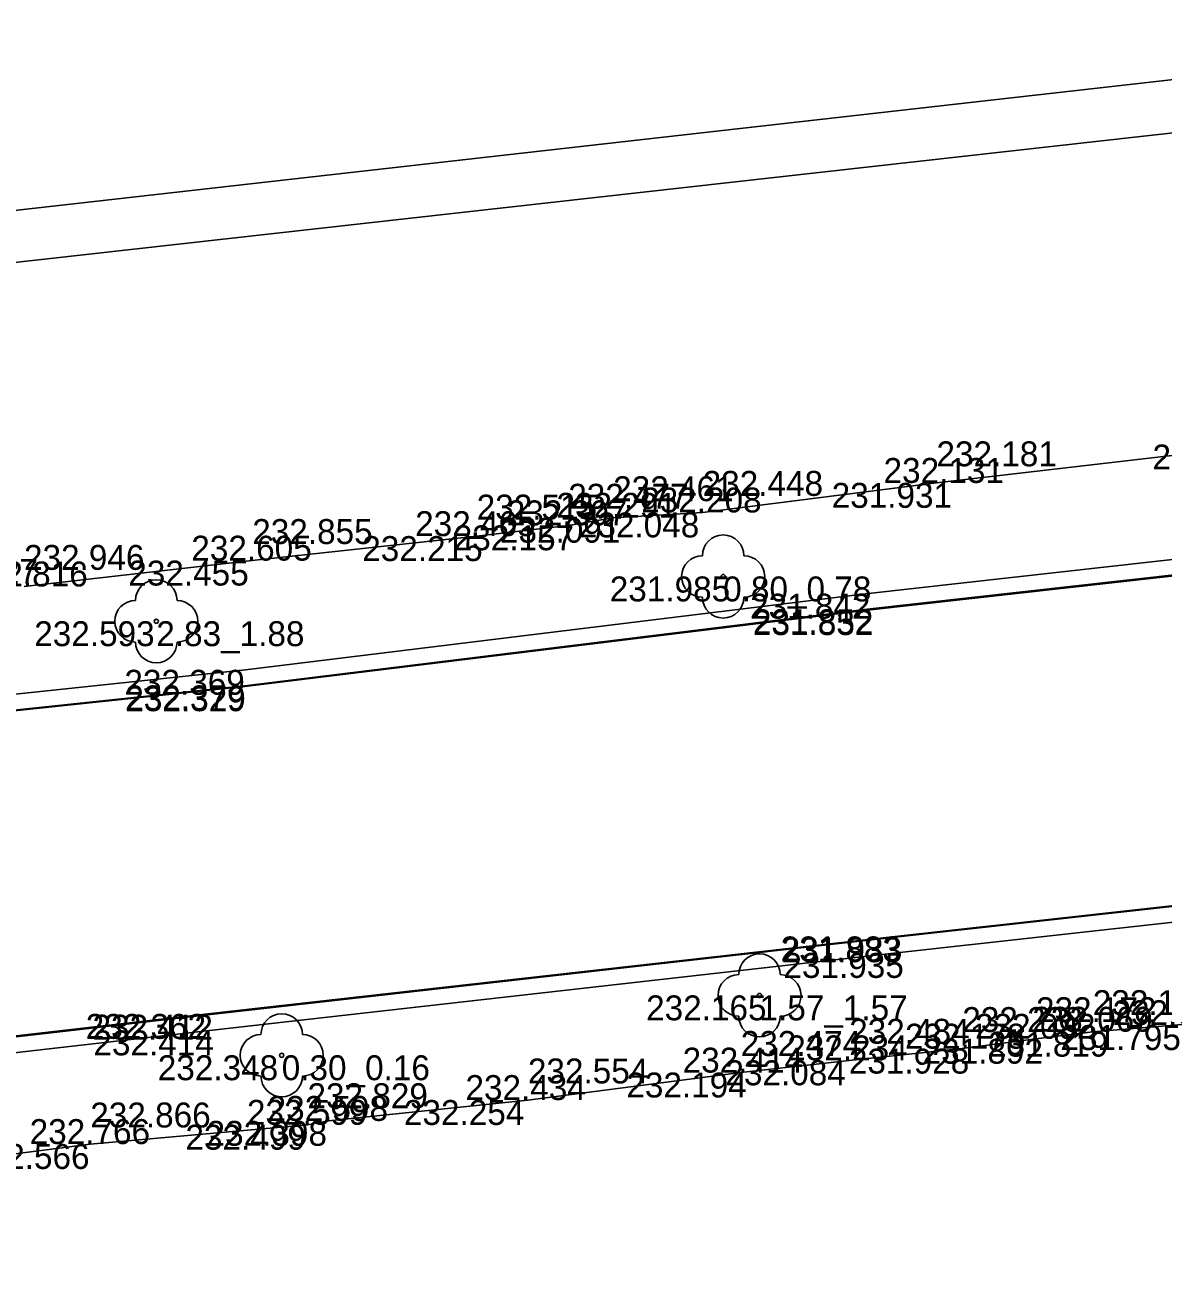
# Model space of a CAD drawing. Extents: x -599516 to -599132, y -1163668 to -1163119.
# Drawn here: x -599469.23 to -599455.52, y -1163522.85 to -1163507.88 of the extents above; entities that cross this region are included whole.
import ezdxf

# ---------------------------------------------------------------- set-up
doc = ezdxf.new("R2010")
doc.units = 0
for name, color, linetype in [('Bod-oznac1', 7, 'Continuous'), ('Bod-oznac2', 7, 'Continuous'), ('Bod-oznac3', 7, 'Continuous'), ('Bod-vyska1', 7, 'Continuous'), ('Bod-vyska2', 7, 'Continuous'), ('Bod-vyska3', 7, 'Continuous'), ('Z_cela-hrobu-dolni-linie', 7, 'Continuous'), ('Z_cela-hrobu-horni-linie', 7, 'Continuous'), ('Z_komunikace', 7, 'Continuous'), ('Z_obvod-kmene-spodek-ve-vysce1_2m', 7, 'Continuous'), ('Z_stromy-kere', 7, 'Continuous'), ('Z_zdi-ohradni', 7, 'Continuous'), ('Z_zpevnene-plochy', 7, 'Continuous')]:
    doc.layers.add(name, color=color, linetype=linetype)

msp = doc.modelspace()

# ---------------------------------------------------------------- linework, layer by layer
at = {"layer": 'Bod-oznac1'}
for p, q in [((-599458.25, -1163513.395), (-599458.25, -1163513.395)), ((-599461.066, -1163513.751), (-599461.066, -1163513.751)), ((-599462.685, -1163513.906), (-599462.685, -1163513.906)), ((-599462.144, -1163513.815), (-599462.144, -1163513.815)), ((-599463.788, -1163514.036), (-599463.788, -1163514.036)), ((-599466.491, -1163514.331), (-599466.491, -1163514.331)), ((-599460.819, -1163514.522), (-599460.819, -1163514.522)), ((-599459.106, -1163514.729), (-599459.106, -1163514.729)), ((-599459.083, -1163514.917), (-599459.083, -1163514.917)), ((-599459.082, -1163514.927), (-599459.082, -1163514.927)), ((-599467.647, -1163515.061), (-599467.647, -1163515.061)), ((-599466.572, -1163515.646), (-599466.572, -1163515.646)), ((-599466.55, -1163515.834), (-599466.55, -1163515.834)), ((-599466.549, -1163515.844), (-599466.549, -1163515.844)), ((-599458.749, -1163518.857), (-599458.749, -1163518.857)), ((-599458.748, -1163518.867), (-599458.748, -1163518.867)), ((-599458.727, -1163519.056), (-599458.727, -1163519.056)), ((-599460.381, -1163519.567), (-599460.381, -1163519.567)), ((-599467.027, -1163519.79), (-599467.027, -1163519.79)), ((-599467.026, -1163519.8), (-599467.026, -1163519.8)), ((-599467.004, -1163519.989), (-599467.004, -1163519.989)), ((-599456.367, -1163520.004), (-599456.367, -1163520.004)), ((-599457.939, -1163520.208), (-599457.939, -1163520.208)), ((-599457.051, -1163520.089), (-599457.051, -1163520.089)), ((-599466.136, -1163520.288), (-599466.136, -1163520.288)), ((-599459.301, -1163520.349), (-599459.301, -1163520.349)), ((-599460.607, -1163520.496), (-599460.607, -1163520.496)), ((-599463.171, -1163520.827), (-599463.171, -1163520.827)), ((-599465.571, -1163521.078), (-599465.571, -1163521.078)), ((-599465.826, -1163521.125), (-599465.826, -1163521.125)), ((-599468.442, -1163521.357), (-599468.442, -1163521.357))]:
    msp.add_line(p, q, dxfattribs=at)
at = {"layer": 'Bod-oznac2'}
for p, q in [((-599458.25, -1163513.395), (-599458.25, -1163513.395)), ((-599461.066, -1163513.751), (-599461.066, -1163513.751)), ((-599462.685, -1163513.906), (-599462.685, -1163513.906)), ((-599462.144, -1163513.815), (-599462.144, -1163513.815)), ((-599463.788, -1163514.036), (-599463.788, -1163514.036)), ((-599466.491, -1163514.331), (-599466.491, -1163514.331)), ((-599456.367, -1163520.004), (-599456.367, -1163520.004)), ((-599457.939, -1163520.208), (-599457.939, -1163520.208)), ((-599457.051, -1163520.089), (-599457.051, -1163520.089)), ((-599459.301, -1163520.349), (-599459.301, -1163520.349)), ((-599460.607, -1163520.496), (-599460.607, -1163520.496)), ((-599463.171, -1163520.827), (-599463.171, -1163520.827)), ((-599465.571, -1163521.078), (-599465.571, -1163521.078)), ((-599465.826, -1163521.125), (-599465.826, -1163521.125)), ((-599468.442, -1163521.357), (-599468.442, -1163521.357))]:
    msp.add_line(p, q, dxfattribs=at)
at = {"layer": 'Bod-oznac3'}
for p, q in [((-599458.25, -1163513.395), (-599458.25, -1163513.395)), ((-599461.066, -1163513.751), (-599461.066, -1163513.751)), ((-599462.685, -1163513.906), (-599462.685, -1163513.906)), ((-599462.144, -1163513.815), (-599462.144, -1163513.815)), ((-599463.788, -1163514.036), (-599463.788, -1163514.036)), ((-599466.491, -1163514.331), (-599466.491, -1163514.331)), ((-599456.367, -1163520.004), (-599456.367, -1163520.004)), ((-599457.939, -1163520.208), (-599457.939, -1163520.208)), ((-599457.051, -1163520.089), (-599457.051, -1163520.089)), ((-599459.301, -1163520.349), (-599459.301, -1163520.349)), ((-599460.607, -1163520.496), (-599460.607, -1163520.496)), ((-599463.171, -1163520.827), (-599463.171, -1163520.827)), ((-599465.826, -1163521.125), (-599465.826, -1163521.125)), ((-599468.442, -1163521.357), (-599468.442, -1163521.357))]:
    msp.add_line(p, q, dxfattribs=at)
at = {"layer": 'Z_cela-hrobu-dolni-linie'}
for points in [[(-599435.23, -1163510.833), (-599438.008, -1163511.099), (-599439.418, -1163511.294), (-599442.084, -1163511.555), (-599442.667, -1163511.633), (-599443.058, -1163511.684), (-599443.507, -1163511.738), (-599444.573, -1163511.832), (-599445.156, -1163511.901), (-599446.188, -1163512.018), (-599447.56, -1163512.189), (-599449.119, -1163512.348), (-599449.987, -1163512.469), (-599451.605, -1163512.656), (-599454.27, -1163512.933), (-599458.25, -1163513.395), (-599461.066, -1163513.751), (-599462.144, -1163513.815), (-599462.685, -1163513.906), (-599463.788, -1163514.036), (-599466.491, -1163514.331), (-599469.24, -1163514.642)], [(-599470.95, -1163521.715), (-599470.845, -1163521.668), (-599468.442, -1163521.357), (-599465.826, -1163521.125), (-599465.571, -1163521.078), (-599463.171, -1163520.827), (-599460.607, -1163520.496), (-599459.301, -1163520.349), (-599457.939, -1163520.208), (-599457.051, -1163520.089), (-599456.367, -1163520.004), (-599455.388, -1163519.925), (-599454.061, -1163519.809), (-599451.356, -1163519.55)]]:
    msp.add_lwpolyline(points, dxfattribs=at)
at = {"layer": 'Z_cela-hrobu-horni-linie'}
for points in [[(-599454.27, -1163512.933), (-599458.25, -1163513.395), (-599458.25, -1163513.395), (-599461.066, -1163513.751), (-599461.066, -1163513.751), (-599462.144, -1163513.815), (-599462.144, -1163513.815), (-599462.685, -1163513.906), (-599462.685, -1163513.906), (-599463.788, -1163514.036), (-599463.788, -1163514.036), (-599466.491, -1163514.331), (-599466.491, -1163514.331), (-599469.24, -1163514.642)], [(-599470.845, -1163521.668), (-599468.442, -1163521.357), (-599468.442, -1163521.357), (-599465.826, -1163521.125), (-599465.826, -1163521.125), (-599465.571, -1163521.078), (-599463.171, -1163520.827), (-599463.171, -1163520.827), (-599460.607, -1163520.496), (-599460.607, -1163520.496), (-599459.301, -1163520.349), (-599459.301, -1163520.349), (-599457.939, -1163520.208), (-599457.939, -1163520.208), (-599457.051, -1163520.089), (-599457.051, -1163520.089), (-599456.367, -1163520.004), (-599456.367, -1163520.004), (-599455.388, -1163519.925), (-599455.388, -1163519.925), (-599454.061, -1163519.809), (-599454.061, -1163519.809), (-599451.356, -1163519.55), (-599451.107, -1163522.776)]]:
    msp.add_lwpolyline(points, dxfattribs=at)
at = {"layer": 'Z_komunikace'}
for points in [[(-599473.086, -1163516.534), (-599466.549, -1163515.844), (-599459.082, -1163514.927), (-599451.472, -1163514.076), (-599444.032, -1163513.231), (-599437.09, -1163512.446), (-599427.751, -1163511.414), (-599421.407, -1163510.664)], [(-599421.581, -1163514.662), (-599428.36, -1163515.423), (-599434.819, -1163516.148), (-599441.683, -1163516.929), (-599449.913, -1163517.876), (-599458.749, -1163518.857), (-599467.027, -1163519.79), (-599473.501, -1163520.532), (-599473.927, -1163520.461), (-599474.378, -1163520.597), (-599474.641, -1163520.812), (-599479.573, -1163521.271)]]:
    msp.add_lwpolyline(points, dxfattribs=at)
at = {"layer": 'Z_stromy-kere'}
for centre in [(-599460.819, -1163514.522), (-599467.647, -1163515.061), (-599460.381, -1163519.567), (-599466.136, -1163520.288)]:
    msp.add_circle(centre, 0.025, dxfattribs=at)
for centre, start, end in [((-599460.819, -1163514.272), 0, 180), ((-599461.069, -1163514.522), 90, 270), ((-599460.569, -1163514.522), 270, 90), ((-599467.647, -1163514.811), 0, 180), ((-599467.897, -1163515.061), 90, 270), ((-599467.397, -1163515.061), 270, 90), ((-599460.819, -1163514.772), 180, 0), ((-599467.647, -1163515.311), 180, 0), ((-599460.381, -1163519.317), 0, 180), ((-599460.631, -1163519.567), 90, 270), ((-599460.131, -1163519.567), 270, 90), ((-599466.136, -1163520.038), 0, 180), ((-599460.381, -1163519.817), 180, 0), ((-599466.386, -1163520.288), 90, 270), ((-599465.886, -1163520.288), 270, 90), ((-599466.136, -1163520.538), 180, 0)]:
    msp.add_arc(centre, 0.25, start, end, dxfattribs=at)
at = {"layer": 'Z_zdi-ohradni'}
for p, q in [((-599421.833, -1163504.754), (-599479.244, -1163511.228)), ((-599479.185, -1163511.843), (-599421.751, -1163505.409))]:
    msp.add_line(p, q, dxfattribs=at)
at = {"layer": 'Z_zpevnene-plochy'}
for points in [[(-599473.087, -1163516.524), (-599473.107, -1163516.335), (-599466.572, -1163515.646), (-599459.106, -1163514.729), (-599451.495, -1163513.878), (-599444.055, -1163513.033), (-599437.113, -1163512.248), (-599427.774, -1163511.216), (-599421.459, -1163510.469), (-599421.021, -1163510.284), (-599420.396, -1163509.389), (-599420.24, -1163509.498)], [(-599473.087, -1163516.524), (-599466.55, -1163515.834), (-599459.083, -1163514.917), (-599451.473, -1163514.066), (-599444.033, -1163513.221), (-599437.091, -1163512.436), (-599427.752, -1163511.404), (-599421.41, -1163510.654), (-599420.897, -1163510.438), (-599420.24, -1163509.498)], [(-599419.671, -1163519.873), (-599419.717, -1163516.476), (-599420.045, -1163515.835), (-599420.256, -1163515.089), (-599420.887, -1163514.692), (-599421.581, -1163514.672), (-599428.359, -1163515.433), (-599434.818, -1163516.158), (-599441.682, -1163516.939), (-599449.912, -1163517.886), (-599458.748, -1163518.867), (-599467.026, -1163519.8), (-599473.501, -1163520.542), (-599473.926, -1163520.471), (-599474.373, -1163520.606), (-599474.637, -1163520.822), (-599479.572, -1163521.281), (-599480.282, -1163521.415), (-599480.802, -1163521.956), (-599481.292, -1163522.751)], [(-599419.671, -1163519.873), (-599419.861, -1163519.876), (-599419.906, -1163516.524), (-599420.223, -1163515.904), (-599420.418, -1163515.211), (-599420.944, -1163514.88), (-599421.573, -1163514.862), (-599428.338, -1163515.622), (-599434.796, -1163516.347), (-599441.66, -1163517.128), (-599449.89, -1163518.075), (-599458.727, -1163519.056), (-599467.004, -1163519.989), (-599473.506, -1163520.734), (-599473.914, -1163520.666), (-599474.282, -1163520.777), (-599474.562, -1163521.005), (-599479.545, -1163521.469), (-599480.187, -1163521.591), (-599480.651, -1163522.073), (-599481.13, -1163522.851), (-599481.292, -1163522.751)]]:
    msp.add_lwpolyline(points, dxfattribs=at)

# ---------------------------------------------------------------- texts
at = {"layer": 'Bod-vyska1'}
for s, p in [('231.684', (-599455.648, -1163513.233)), ('231.931', (-599459.512, -1163513.695)), ('232.048', (-599462.557, -1163514.051)), ('232.157', (-599464.064, -1163514.206)), ('232.091', (-599463.508, -1163514.115)), ('232.215', (-599465.166, -1163514.336)), ('232.455', (-599467.984, -1163514.631)), ('231.985', (-599462.185, -1163514.822)), ('231.842', (-599460.495, -1163515.029)), ('231.852', (-599460.461, -1163515.217)), ('231.832', (-599460.46, -1163515.227)), ('232.593', (-599469.117, -1163515.361)), ('232.369', (-599468.031, -1163515.946)), ('232.379', (-599468.022, -1163516.134)), ('232.329', (-599468.019, -1163516.144)), ('231.883', (-599460.127, -1163519.157)), ('231.933', (-599460.114, -1163519.167)), ('231.935', (-599460.093, -1163519.356)), ('232.165', (-599461.747, -1163519.867)), ('232.362', (-599468.497, -1163520.09)), ('232.412', (-599468.415, -1163520.1)), ('231.795', (-599456.756, -1163520.225)), ('232.414', (-599468.404, -1163520.289)), ('231.819', (-599457.629, -1163520.304)), ('231.928', (-599459.305, -1163520.508)), ('231.892', (-599458.417, -1163520.389)), ('232.348', (-599467.629, -1163520.588)), ('232.084', (-599460.792, -1163520.649)), ('232.194', (-599461.985, -1163520.796)), ('232.254', (-599464.664, -1163521.127)), ('232.499', (-599467.296, -1163521.425)), ('232.398', (-599467.041, -1163521.378)), ('232.566', (-599469.901, -1163521.657))]:
    msp.add_text(s, height=0.3, dxfattribs=at).set_placement(p)
at = {"layer": 'Bod-vyska2'}
for s, p in [('232.131', (-599458.887, -1163513.395)), ('232.208', (-599461.806, -1163513.751)), ('232.307', (-599463.426, -1163513.906)), ('232.291', (-599462.827, -1163513.815)), ('232.465', (-599464.529, -1163514.036)), ('232.605', (-599467.225, -1163514.331)), ('232.816', (-599469.923, -1163514.642)), ('232.075', (-599456.129, -1163519.925)), ('232.069', (-599457.095, -1163520.004)), ('232.178', (-599458.629, -1163520.208)), ('232.092', (-599457.785, -1163520.089)), ('232.234', (-599460.047, -1163520.349)), ('232.414', (-599461.307, -1163520.496)), ('232.434', (-599463.923, -1163520.827)), ('232.599', (-599466.555, -1163521.125)), ('232.598', (-599466.306, -1163521.078)), ('232.766', (-599469.172, -1163521.357))]:
    msp.add_text(s, height=0.3, dxfattribs=at).set_placement(p)
at = {"layer": 'Bod-vyska3'}
for s, p in [('232.181', (-599458.25, -1163513.195)), ('232.461', (-599462.144, -1163513.615)), ('232.448', (-599461.066, -1163513.551)), ('232.477', (-599462.685, -1163513.706)), ('232.515', (-599463.788, -1163513.836)), ('232.855', (-599466.491, -1163514.131)), ('232.946', (-599469.24, -1163514.442)), ('233.127', (-599470.522, -1163514.61)), ('232.172', (-599457.051, -1163519.889)), ('232.119', (-599456.367, -1163519.804)), ('232.228', (-599457.939, -1163520.008)), ('232.484', (-599459.301, -1163520.149)), ('232.474', (-599460.607, -1163520.296)), ('232.554', (-599463.171, -1163520.627)), ('232.829', (-599465.826, -1163520.925)), ('232.866', (-599468.442, -1163521.157))]:
    msp.add_text(s, height=0.3, dxfattribs=at).set_placement(p)
at = {"layer": 'Z_obvod-kmene-spodek-ve-vysce1_2m'}
for s, p in [('0.80_0.78', (-599460.819, -1163514.822)), ('2.83_1.88', (-599467.647, -1163515.361)), ('1.57_1.57', (-599460.381, -1163519.867)), ('0.30_0.16', (-599466.136, -1163520.588))]:
    msp.add_text(s, height=0.3, dxfattribs=at).set_placement(p)

doc.saveas('drawing.dxf')
